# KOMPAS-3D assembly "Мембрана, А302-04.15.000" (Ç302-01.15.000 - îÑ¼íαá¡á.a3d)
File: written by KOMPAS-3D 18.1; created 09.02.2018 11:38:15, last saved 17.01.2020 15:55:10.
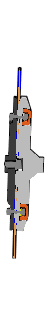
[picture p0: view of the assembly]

Document properties: Автор: Милов; Полное имя файла: D:\Мембранные насосы\Мембранный электропривод\А302-00.00.000 - ASTRA-302 (МЭ200)\3Д ПВХ\А302-01.15.000 - Мембрана.a3d

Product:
- Part/product: Мембрана  | designation А302-04.15.000  | pos. 0
    Масса: 2.46802
    Раздел спецификации: Сборочные единицы
    Форматы листов документа: A3
    source file: ..\А302-04.00.000 - Мембранный насос ASTRA-302-PP\А302-04.15.000 - Мембрана.cdw
  - Component [detail]: Заглушка  | designation А302-03.15.007  | qty 8  | pos. 5  | Масса: 0.00317916; Раздел спецификации: Детали; Форматы листов документа: A4; source file: ..\Чертежи Полипропилен\А302-03.15.007 - Заглушка.cdw, А302-01.15.007 - Заглушка.m3d
  - Component [detail]: Гайка шестигранная самостопорящаяся с фланцем / DIN 6927-M5-A2-70  | qty 2  | pos. 9  | Масса: 0.000241945; Раздел спецификации: Стандартные изделия; Примечание: Нерж. / насечки; source file: ..\..\..\..\2 Стандартные изделия 3D\Гайки\DIN 6927\Гайка шестигранная самостопорящаяся с фланцем DIN 6927-M5 - A2-70.m3d
  - Component [detail]: Кольцо плоское  / уплотнительное 5-13-10 Ф4  | designation А302-01.15.008  | qty 8  | pos. 6  | Материал: Фторопласт-4  ГОСТ 10007-80 Е (density 2200 kg/m3); Масса: 0.000126921; Раздел спецификации: Детали; Форматы листов документа: A4; source file: А302-01.15.008 - Кольцо плоское Ф4.m3d, А302-01.15.008 - Кольцо плоское уплотнительное 5-13-10 Ф4.cdw
  - Component [standard]: Болт с шестигранной головкой с фланцем ГОСТ Р 55739-М5 x 25-A2-70  | qty 8  | pos. 41  | Масса: 0.00626538; Раздел спецификации: Стандартные изделия; Рассекать на разрезах: no; additional columns: ГОСТ Р 55739-2013; М5 x 25 - A2-70; Нержавеющая сталь
  - Component [detail]: Мембрана  | designation А302-04.15.001  | qty 2  | pos. 2  | Материал: Фторопласт-4  ГОСТ 10007-80 Е (density 2200 kg/m3); Масса: 0.132112; Раздел спецификации: Детали; Форматы листов документа: A4
  - Component [detail]: Шайба  | designation А302-04.15.003  | pos. 4  | Материал: Полипропилен  ГОСТ 26996-86 (density 900 kg/m3); Масса: 0.247573; Раздел спецификации: Детали; Форматы листов документа: A3; source file: А302-01.15.003 - Шайба.m3d
  - Component [detail]: Мембрана  | designation А302-04.15.001  | pos. 1  | Масса: 0.264223; Раздел спецификации: Детали; Форматы листов документа: A4
  - Component [assembly]: Упор  | designation А302-04.15.002  | pos. 48  | Материал: Сталь 12Х18Н10Т ГОСТ 5632-72 (density 7900 kg/m3); Масса: 1.61349; Раздел спецификации: Детали; Форматы листов документа: A3; source file: ..\А302-04.00.000 - Мембранный насос ASTRA-302-PP\А302-04.15.002 - Упор.cdw, А302-01.15.002 - Упор.a3d
- Part/product: Мембрана  | designation А302-03.15.000  | pos. 0
    Масса: 2.49914
    Раздел спецификации: Сборочные единицы
    Форматы листов документа: A3
    source file: ..\Чертежи Полипропилен\А302-03.15.000 - Мембрана.cdw
  - Component [assembly]: Упор  | designation А302-02.15.002  | pos. 48  | Материал: Сталь 12Х18Н10Т ГОСТ 5632-72 (density 7900 kg/m3); Масса: 1.61349; Раздел спецификации: Детали; Форматы листов документа: A3; source file: А302-01.15.002 - Упор.a3d, А302-02.00.000 - ASTRA-302 (МЭ200)\А302-02.15.002 - Упор.cdw
  - Component [detail]: Мембрана  | designation А302-02.15.001  | pos. 1  | Масса: 0.264223; Раздел спецификации: Детали; Форматы листов документа: A4
  - Component [detail]: Шайба  | designation А302-03.15.003  | pos. 4  | Материал: Полипропилен  ГОСТ 26996-86 (density 900 kg/m3); Масса: 0.28231; Раздел спецификации: Детали; Форматы листов документа: A3; source file: ..\Чертежи Полипропилен\А302-03.15.003 - Шайба.cdw, А302-01.15.003 - Шайба.m3d
  - Component [standard]: Болт с шестигранной головкой с фланцем ГОСТ Р 55739-М5 x 20-A2-70  | qty 6  | pos. 41  | Масса: 0.00626538; Раздел спецификации: Стандартные изделия; Рассекать на разрезах: no; additional columns: ГОСТ Р 55739-2013; М5 x 20 - A2-70; Нержавеющая сталь
  - Component [detail]: Кольцо плоское  / уплотнительное 5-13-10 Ф4  | designation А302-01.15.008  | qty 6  | pos. 6  | Материал: Фторопласт-4  ГОСТ 10007-80 Е (density 2200 kg/m3); Масса: 0.000126921; Раздел спецификации: Детали; Форматы листов документа: A4; source file: А302-01.15.008 - Кольцо плоское Ф4.m3d, А302-01.15.008 - Кольцо плоское уплотнительное 5-13-10 Ф4.cdw
  - Component [detail]: Заглушка  | designation А302-03.15.007  | qty 6  | pos. 5  | Масса: 0.00317916; Раздел спецификации: Детали; Форматы листов документа: A4; source file: ..\Чертежи Полипропилен\А302-03.15.007 - Заглушка.cdw, А302-01.15.007 - Заглушка.m3d
- Part/product: Мембрана  | designation А302-01.15.000  | pos. 0
    Масса: 1.24048
    Раздел спецификации: Сборочные единицы
    Форматы листов документа: A3
    source file: \\192.168.87.28\Konstructor_doc\Мембранные насосы\Мембранный электропривод\А302-00.00.000 - ASTRA-302 (МЭ200)\3Д ПВХ\А302-01.15.000 - Мембрана.cdw
  - Component: Лента ФУМ  | pos. 12  | Раздел спецификации: Материалы; Примечание: мм
  - Component [detail]: Мембрана  | designation А302-01.15.001  | pos. 1  | Масса: 0.266387; Раздел спецификации: Детали; Форматы листов документа: A4; source file: А302-01.15.001 - Мембрана.cdw, А302-01.15.001 - Мембрана.m3d
  - Component [detail]: Шайба  | designation А302-01.15.003  | pos. 4  | Масса: 0.292092; Раздел спецификации: Детали; Форматы листов документа: A4; source file: А302-01.15.003 - Шайба.m3d
  - Component [detail]: Упор  | designation А302-01.15.002  | pos. 3  | Масса: 0.395725; Раздел спецификации: Детали; Форматы листов документа: A3; source file: А302-01.15.002 - Упор.m3d
  - Component [standard]: Болт с шестигранной головкой с фланцем  / ГОСТ Р  55739-М5 x 25-A2-70  | qty 6  | pos. 10
      Материал: Нержавеющая сталь (density 1000 kg/m3)
      Масса: 0.000898962
      Раздел спецификации: Стандартные изделия
      Примечание: Нерж.
      additional columns: ГОСТ Р 55739-2013; М5 x 25 - A2-70; Нержавеющая сталь
      source file: C:\Program Files\ASCON\KOMPAS-3D v18\Libs\PartLib\DATA\VAULT\methods\kompas\3d\PLib_Bolt_1_ISO_1100.m3d
  - Component [detail]: Гайка шестигранная самостопорящаяся с фланцем / DIN 6927-M5-A2-70  | qty 6  | pos. 9  | Масса: 0.000241945; Раздел спецификации: Стандартные изделия; Примечание: Нерж. / насечки; source file: ..\..\..\..\2 Стандартные изделия 3D\Гайки\DIN 6927\Гайка шестигранная самостопорящаяся с фланцем DIN 6927-M5 - A2-70.m3d
  - Component [detail]: Кольцо плоское  / уплотнительное 5-13-10 Ф4  | designation А302-01.15.008  | qty 6  | pos. 6  | Материал: Фторопласт-4  ГОСТ 10007-80 Е (density 2200 kg/m3); Масса: 0.000126921; Раздел спецификации: Детали; Форматы листов документа: A4; source file: А302-01.15.008 - Кольцо плоское Ф4.m3d, А302-01.15.008 - Кольцо плоское уплотнительное 5-13-10 Ф4.cdw
  - Component [standard]: Болт с шестигранной головкой с фланцем  / ГОСТ Р  55739-М8 x 30-A2-70  | pos. 11
      Материал: Нержавеющая сталь (density 1000 kg/m3)
      Масса: 0.00287962
      Раздел спецификации: Стандартные изделия
      Примечание: Нерж.
      additional columns: ГОСТ Р 55739-2013; М8 x 30 - A2-70; Нержавеющая сталь
      source file: C:\Program Files\ASCON\KOMPAS-3D v18\Libs\PartLib\DATA\VAULT\methods\kompas\3d\PLib_Bolt_1_ISO_1100.m3d
  - Component [detail]: Кольцо плоское Ф4  | designation А302-01.15.009  | pos. 7  | Материал: Фторопласт-4  ГОСТ 10007-80 Е (density 2200 kg/m3); Масса: 0.000197116; Раздел спецификации: Детали; Форматы листов документа: A4; source file: А302-01.15.009 - Кольцо плоское Ф4.m3d
  - Component [detail]: Мембрана  | designation А302-01.15.001-01  | qty 2  | pos. 2  | Материал: Фторопласт-4  ГОСТ 10007-80 Е (density 2200 kg/m3); Масса: 0.132198; Раздел спецификации: Детали; Форматы листов документа: A4; source file: А302-01.15.001 - Мембрана.cdw, А302-01.15.001-01- Мембрана.m3d
  - Component [detail]: Заглушка  | designation А302-01.15.007  | qty 6  | pos. 5  | Масса: 0.00113785; Раздел спецификации: Детали; Форматы листов документа: A4; source file: А302-01.15.007 - Заглушка.cdw, А302-01.15.007 - Заглушка.m3d
  - Component [detail]: Заглушка резьбовая  | designation А302-01.15.011  | pos. 8  | Масса: 0.00237469; Раздел спецификации: Детали; Форматы листов документа: A4; source file: \\192.168.87.28\Konstructor_doc\Мембранные насосы\Мембранный электропривод\А302-00.00.000 - ASTRA-302 (МЭ200)\3Д ПВХ\А302-01.15.011 - Заглушка резьбовая.cdw, А302-01.15.011 - Заглушка резьбовая.cdw, А302-01.15.011 - Заглушка резьбовая.m3d
- Part/product: Мембрана  | designation А302-02.15.000  | pos. 0
    Масса: 2.44278
    Раздел спецификации: Сборочные единицы
    Форматы листов документа: A3
    source file: ..\Чертежи ПВХ\А302-02.15.000 - Мембрана.cdw, А302-02.00.000 - ASTRA-302 (МЭ200)\А302-02.15.000 - Мембрана.cdw
  - Component [detail]: Заглушка  | designation А302-01.15.007  | qty 6  | pos. 5  | Масса: 0.00113785; Раздел спецификации: Детали; Форматы листов документа: A4; source file: А302-01.15.007 - Заглушка.cdw, А302-01.15.007 - Заглушка.m3d
  - Component [detail]: Заглушка резьбовая  | designation А302-01.15.011  | pos. 8  | Раздел спецификации: Детали; Форматы листов документа: A4; source file: А302-01.15.011 - Заглушка резьбовая.m3d
  - Component [detail]: Мембрана  | designation А302-02.15.001-01  | qty 2  | pos. 2  | Материал: Фторопласт-4  ГОСТ 10007-80 Е (density 2200 kg/m3); Масса: 0.132198; Раздел спецификации: Детали; Форматы листов документа: A4; source file: А302-01.15.001-01- Мембрана.m3d
  - Component [detail]: Кольцо плоское  / уплотнительное 5-13-10 Ф4  | designation А302-01.15.008  | qty 6  | pos. 6  | Материал: Фторопласт-4  ГОСТ 10007-80 Е (density 2200 kg/m3); Масса: 0.000126921; Раздел спецификации: Детали; Форматы листов документа: A4; source file: А302-01.15.008 - Кольцо плоское Ф4.m3d, А302-01.15.008 - Кольцо плоское уплотнительное 5-13-10 Ф4.cdw
  - Component [standard]: Болт с шестигранной головкой с фланцем ГОСТ Р 55739-М5 x 20-A2-70  | qty 6  | pos. 41  | Масса: 0.00626538; Раздел спецификации: Стандартные изделия; Рассекать на разрезах: no; additional columns: ГОСТ Р 55739-2013; М5 x 20 - A2-70; Нержавеющая сталь
  - Component [detail]: Упор  | designation А302-02.15.002  | pos. 3  | Материал: Сталь 12Х18Н10Т ГОСТ 5632-72 (density 0 kg/m3); Раздел спецификации: Детали; Форматы листов документа: A3; source file: А302-01.15.002 - Упор.m3d, А302-02.00.000 - ASTRA-302 (МЭ200)\А302-02.15.002 - Упор.cdw
  - Component [detail]: Шайба  | designation А302-02.15.003  | pos. 4  | Материал: Полипропилен  ГОСТ 26996-86 (density 900 kg/m3); Масса: 0.251914; Раздел спецификации: Детали; Форматы листов документа: A4
  - Component [detail]: Мембрана  | designation А302-02.15.001  | pos. 1  | Масса: 0.264223; Раздел спецификации: Детали; Форматы листов документа: A4
  - Component [assembly]: Упор  | designation А302-02.15.002  | pos. 48  | Материал: Сталь 12Х18Н10Т ГОСТ 5632-72 (density 7900 kg/m3); Масса: 1.61349; Раздел спецификации: Детали; Форматы листов документа: A3; source file: А302-01.15.002 - Упор.a3d, А302-02.00.000 - ASTRA-302 (МЭ200)\А302-02.15.002 - Упор.cdw
- Part/product: Мембрана  | designation А302-05.15.000  | pos. 0
    Масса: 2.20411
    Раздел спецификации: Сборочные единицы
    Форматы листов документа: A3
    source file: ..\А302-05.00.000 - Мембранный насос ASTRA-302-PVC\А302-05.15.000 - Мембрана.cdw
  - Component [assembly]: Упор  | designation А302-04.15.002  | pos. 48  | Материал: Сталь 12Х18Н10Т ГОСТ 5632-72 (density 7900 kg/m3); Масса: 1.61349; Раздел спецификации: Детали; Форматы листов документа: A3; source file: ..\А302-04.00.000 - Мембранный насос ASTRA-302-PP\А302-04.15.002 - Упор.cdw, А302-01.15.002 - Упор.a3d
  - Component [detail]: Мембрана  | designation А302-04.15.001  | pos. 1  | Масса: 0.264223; Раздел спецификации: Детали; Форматы листов документа: A4
  - Component [detail]: Шайба  | designation А302-05.15.003  | pos. 4  | Материал: Поливинилхлорид (density 0 kg/m3); Раздел спецификации: Детали; Форматы листов документа: A3; source file: ..\А302-04.00.000 - Мембранный насос ASTRA-302-PP\А302-04.15.003 - Шайба.cdw, ..\Чертежи ПВХ\А302-02.15.003 - Шайба.cdw, ..\Чертежи Полипропилен\А302-03.15.003 - Шайба.cdw, А302-01.15.003 - Шайба.m3d
  - Component [standard]: Болт с шестигранной головкой с фланцем ГОСТ Р 55739-М5 x 25-A2-70  | qty 8  | pos. 41  | Масса: 0.00626538; Раздел спецификации: Стандартные изделия; Рассекать на разрезах: no; additional columns: ГОСТ Р 55739-2013; М5 x 25 - A2-70; Нержавеющая сталь
  - Component [detail]: Кольцо плоское  / уплотнительное 5-13-10 Ф4  | designation А302-01.15.008  | qty 8  | pos. 6  | Материал: Фторопласт-4  ГОСТ 10007-80 Е (density 2200 kg/m3); Масса: 0.000126921; Раздел спецификации: Детали; Форматы листов документа: A4; source file: А302-01.15.008 - Кольцо плоское Ф4.m3d, А302-01.15.008 - Кольцо плоское уплотнительное 5-13-10 Ф4.cdw
  - Component [detail]: Мембрана  | designation А302-04.15.001  | qty 2  | pos. 2  | Материал: Фторопласт-4  ГОСТ 10007-80 Е (density 2200 kg/m3); Масса: 0.132112; Раздел спецификации: Детали; Форматы листов документа: A4
  - Component [detail]: Заглушка  | designation А302-01.15.007  | qty 8  | pos. 5  | Масса: 0.00113785; Раздел спецификации: Детали; Форматы листов документа: A4; source file: А302-01.15.007 - Заглушка.cdw, А302-01.15.007 - Заглушка.m3d
- Part/product: Мембрана  | designation А302-04.15.000-07  | pos. 0
    Масса: 2.65346
    Раздел спецификации: Сборочные единицы
    Форматы листов документа: A3
    source file: ..\А302-04.00.000 - Мембранный насос ASTRA-302-PP\А302-04.15.000-7 - Мембрана.cdw
  - Component [assembly]: Упор  | designation А302-04.15.002  | pos. 48  | Материал: Сталь 12Х18Н10Т ГОСТ 5632-72 (density 7900 kg/m3); Масса: 1.61349; Раздел спецификации: Детали; Форматы листов документа: A3; source file: ..\А302-04.00.000 - Мембранный насос ASTRA-302-PP\А302-04.15.002 - Упор.cdw, А302-01.15.002 - Упор.a3d
  - Component [detail]: Мембрана  | designation А302-04.15.001  | pos. 1  | Масса: 0.264223; Раздел спецификации: Детали; Форматы листов документа: A4
  - Component [detail]: Шайба (нарощеннАЯ)  | designation А302-04.15.003-777  | pos. 4  | Материал: Полипропилен  ГОСТ 26996-86 (density 900 kg/m3); Масса: 0.433016; Раздел спецификации: Детали; Форматы листов документа: A3; source file: ..\А302-04.00.000 - Мембранный насос ASTRA-302-PP\А302-04.15.003-777 - Шайба.cdw, А302-01.15.003 - Шайба.m3d
  - Component [standard]: Болт с шестигранной головкой с фланцем ГОСТ Р 55739-М5 x 25-A2-70  | qty 8  | pos. 41  | Масса: 0.00626538; Раздел спецификации: Стандартные изделия; Рассекать на разрезах: no; additional columns: ГОСТ Р 55739-2013; М5 x 25 - A2-70; Нержавеющая сталь
  - Component [detail]: Кольцо плоское  / уплотнительное 5-13-10 Ф4  | designation А302-01.15.008  | qty 8  | pos. 6  | Материал: Фторопласт-4  ГОСТ 10007-80 Е (density 2200 kg/m3); Масса: 0.000126921; Раздел спецификации: Детали; Форматы листов документа: A4; source file: А302-01.15.008 - Кольцо плоское Ф4.m3d, А302-01.15.008 - Кольцо плоское уплотнительное 5-13-10 Ф4.cdw
  - Component [detail]: Мембрана  | designation А302-04.15.001  | qty 2  | pos. 2  | Материал: Фторопласт-4  ГОСТ 10007-80 Е (density 2200 kg/m3); Масса: 0.132112; Раздел спецификации: Детали; Форматы листов документа: A4
  - Component [detail]: Деталь  | pos. 189  | Раздел спецификации: Детали; Форматы листов документа: A3; source file: ..\А302-04.00.000 - Мембранный насос ASTRA-302-PP\А302-04.15.003-08 - Упор.cdw, C:\Users\User\Desktop\Упор из листа 20.m3d

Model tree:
1. Массив по образцу:1  (6 pattern instances)
2. Сечение поверхностью:1  (with: Отверстие:1, Операция вращения:1, Отверстие:3, Вырезать элемент выдавливания:1, Операция выдавливания:1, Вырезать элемент выдавливания:3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)  (labels: v65_h1)

Expressions: A2-70
Referenced files in D:\Мембранные насосы\Мембранный электропривод\А302-00.00.000 - ASTRA-302 (МЭ200)\3Д ПВХ\: А302-01.15.001 - Мембрана.m3d, А302-01.15.001 - Мембрана.cdw, А302-01.15.003 - Шайба.m3d, А302-01.15.002 - Упор.m3d, А302-01.15.008 - Кольцо плоское Ф4.m3d, А302-01.15.008 - Кольцо плоское уплотнительное 5-13-10 Ф4.cdw, А302-01.15.009 - Кольцо плоское Ф4.m3d, А302-01.15.001-01- Мембрана.m3d, А302-01.15.007 - Заглушка.m3d, А302-01.15.007 - Заглушка.cdw, А302-01.15.011 - Заглушка резьбовая.m3d, А302-01.15.011 - Заглушка резьбовая.cdw, А302-01.15.002 - Упор.a3d
Referenced files in C:\Program Files\ASCON\KOMPAS-3D v18\Libs\PartLib\DATA\VAULT\methods\kompas\3d\: PLib_Bolt_1_ISO_1100.m3d
Referenced files in D:\2 Стандартные изделия 3D\Гайки\DIN 6927\: Гайка шестигранная самостопорящаяся с фланцем DIN 6927-M5 - A2-70.m3d
Referenced files in \\192.168.87.28\Konstructor_doc\Мембранные насосы\Мембранный электропривод\А302-00.00.000 - ASTRA-302 (МЭ200)\3Д ПВХ\: А302-01.15.011 - Заглушка резьбовая.cdw, А302-01.15.000 - Мембрана.cdw
Referenced files in D:\Мембранные насосы\Мембранный электропривод\А302-00.00.000 - ASTRA-302 (МЭ200)\3Д ПВХ\А302-02.00.000 - ASTRA-302 (МЭ200)\: А302-02.15.002 - Упор.cdw
Referenced files in D:\Мембранные насосы\Мембранный электропривод\А302-00.00.000 - ASTRA-302 (МЭ200)\Чертежи Полипропилен\: А302-03.15.007 - Заглушка.cdw, А302-03.15.003 - Шайба.cdw
Referenced files in D:\Мембранные насосы\Мембранный электропривод\А302-00.00.000 - ASTRA-302 (МЭ200)\А302-04.00.000 - Мембранный насос ASTRA-302-PP\: А302-04.15.002 - Упор.cdw, А302-04.15.003 - Шайба.cdw, А302-04.15.003-08 - Упор.cdw
Referenced files in D:\Мембранные насосы\Мембранный электропривод\А302-00.00.000 - ASTRA-302 (МЭ200)\Чертежи ПВХ\: А302-02.15.003 - Шайба.cdw
Referenced files in D:\Мембранные насосы\Мембранный электропривод\А302-00.00.000 - ASTRA-302 (МЭ200)\3Д ПВХ\..\А302-04.00.000 - Мембранный насос ASTRA-302-PP\: А302-04.15.003-777 - Шайба.cdw, А302-04.15.002 - Упор.cdw
Referenced files in C:\Users\User\Desktop\: Упор из листа 20.m3d
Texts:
  3D_Doc-graphic.lyt,1.000000-4294967295-203648116615
  Болт с шестигранной головкой с фланцем
  ГОСТ Р  55739-М5 x 25-A2-70
  Гайка шестигранная самостопорящаяся с фланцем
  DIN 6927-M5-A2-70
  Нерж. / насечки
  уплотнительное 5-13-10 Ф4
  ГОСТ Р  55739-М8 x 30-A2-70
  Болт с шестигранной головкой с фланцемГОСТ Р 55739-М5x20-A2-70
  Точка начала. Х
  Точка начала. Y
  Точка начала. Z
  hole1
  hole2
  Деталь (1)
